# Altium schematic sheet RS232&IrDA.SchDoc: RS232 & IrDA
size A4; DocumentNumber: MB1167; Revision: B.1; SheetNumber: 10; SheetTotal: 17; Project: STM327x6G-EVAL
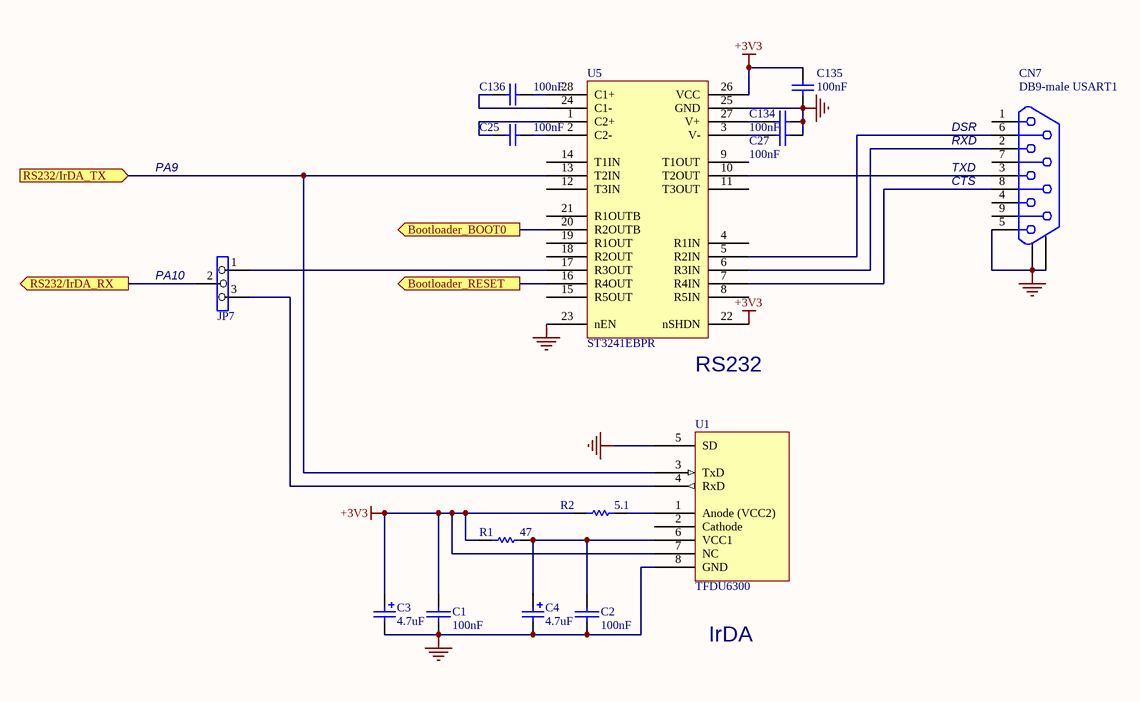
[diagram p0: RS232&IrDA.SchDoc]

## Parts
C1  100nF  [0603C]
C2  100nF  [0603C]
C3  4.7uF  [TAN-A]
C4  4.7uF  [TAN-A]
C25  100nF  [0603C]
C27  100nF  [0603C]
C134  100nF  [0603C]
C135  100nF  [0603C]
C136  100nF  [0603C]
CN7  DB9-male USART1  [DB9/M]
JP7  (no value)  [SIP3]
R1  47  [0603R]
R2  5.1  [0603R]
U1  TFDU6300  [IR_VISHAY3]
U5  ST3241EBPR  [SSOP28_0R65_10R2X7R8]

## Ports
Bootloader_BOOT0 (out), Bootloader_RESET (out), RS232/IrDA_RX (out), RS232/IrDA_TX (in)

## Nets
+3V3: C1.1 C3.1 C135.1 R1.1 R2.1 U1.7(NC) U5.22(nSHDN) U5.26(VCC)
GND: C1.2 C2.2 C3.2 C4.2 C27.1 C134.1 C135.2 CN7.5 CN7.10 CN7.11 U1.5(SD) U1.8(GND) U5.23(nEN) U5.25(GND)
Bootloader_BOOT0: U5.20(R2OUTB) ; port Bootloader_BOOT0
Bootloader_RESET: U5.16(R4OUT) ; port Bootloader_RESET
RS232/IrDA_RX: JP7.2 ; port RS232/IrDA_RX
RS232/IrDA_TX: U1.3(TxD) U5.13(T2IN) ; port RS232/IrDA_TX
NetC2_1: C2.1 C4.1 R1.2 U1.6(VCC1)
NetC25_1: C25.1 U5.1(C2+)
NetC25_2: C25.2 U5.2(C2-)
NetC27_2: C27.2 U5.3(V-)
NetC134_2: C134.2 U5.27(V+)
NetC136_1: C136.1 U5.24(C1-)
NetC136_2: C136.2 U5.28(C1+)
NetCN7_2: CN7.2 U5.6(R3IN)
NetCN7_3: CN7.3 U5.10(T2OUT)
NetCN7_6: CN7.6 U5.5(R2IN)
NetCN7_8: CN7.8 U5.7(R4IN)
NetJP7_1: JP7.1 U5.17(R3OUT)
NetJP7_3: JP7.3 U1.4(RxD)
NetR2_2: R2.2 U1.1(Anode_(VCC2))

Not connected (* = marked no-connect by the designer): CN7 1 4 7 9; U1 2(Cathode); U5 4(R1IN) 8(R5IN) 9(T1OUT) 11(T3OUT) 12(T3IN) 14(T1IN) 15(R5OUT) 18(R2OUT) 19(R1OUT) 21(R1OUTB)

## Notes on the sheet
- PA9
- (near CN7) RXD
- (near CN7) TXD
- (near CN7) DSR
- (near CN7) CTS
- (near JP7) PA10
- (near U5) RS232
- IrDA

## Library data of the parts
C1 C2 = CAP: Capacitor
C3 C4 = Cap Pol1: Polarized Capacitor (Radial); Value: 100pF
C25 C27 C134-C136 = Cap: Capacitor; Value: 10nF
CN7 = DB9-USART
JP7 = Jumper3
R1 R2 = Res1: Resistor; Value: 1K
U1 = TFDU4300
U5 = ST3241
